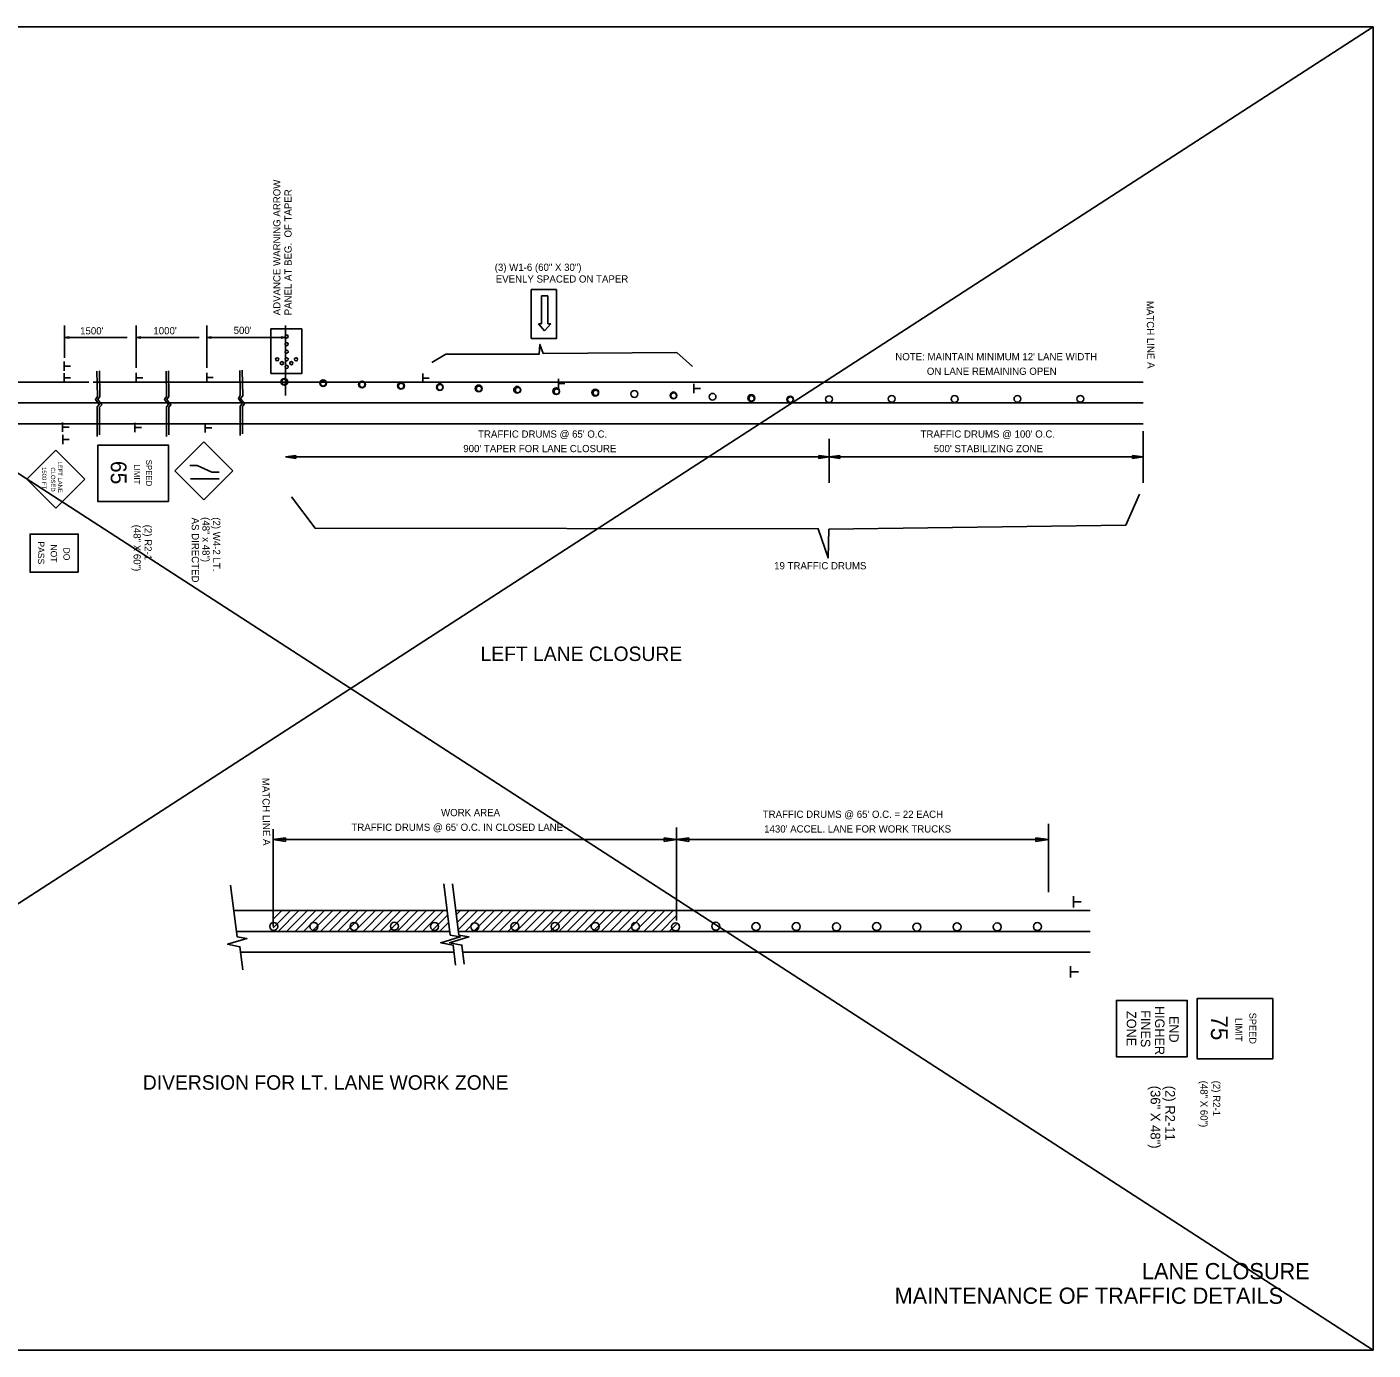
# Model space of a CAD drawing. Extents: x 1374027 to 1374537, y 380415 to 381405.
# Drawn here: x 1374085.2 to 1374197.1, y 380635.2 to 380745.2 of the extents above; entities that cross this region are included whole.
import ezdxf

# ---------------------------------------------------------------- set-up
doc = ezdxf.new("R2010")
doc.units = 0
for name, color, linetype in [('Default', 7, 'Continuous'), ('DSN_DRFT_Junk-No-Plot', 7, 'Continuous'), ('R_Border Notes', 7, 'Continuous'), ('R_MOT', 7, 'Continuous')]:
    doc.layers.add(name, color=color, linetype=linetype)

msp = doc.modelspace()

# ---------------------------------------------------------------- linework, layer by layer
at = {"layer": 'Default'}
for p, q in [((1374127.96, 380722.82), (1374127.96, 380720.49)), ((1374127.96, 380722.82), (1374128.48, 380722.82)), ((1374128.48, 380722.82), (1374128.48, 380720.49)), ((1374088.31, 380720.34), (1374088.31, 380717.66)), ((1374094.28, 380720.34), (1374094.28, 380716.82)), ((1374100.14, 380720.34), (1374100.14, 380716.82)), ((1374106.68, 380720.34), (1374106.68, 380716.82)), ((1374127.96, 380720.49), (1374127.7, 380720.49)), ((1374127.7, 380720.49), (1374128.22, 380719.92)), ((1374128.22, 380719.92), (1374128.74, 380720.49)), ((1374128.48, 380720.49), (1374128.74, 380720.49)), ((1374088.69, 380719.42), (1374088.31, 380719.36)), ((1374088.31, 380719.36), (1374093.53, 380719.36)), ((1374088.69, 380719.3), (1374088.31, 380719.36)), ((1374088.69, 380719.41), (1374088.38, 380719.36)), ((1374088.69, 380719.31), (1374088.38, 380719.36)), ((1374088.69, 380719.4), (1374088.44, 380719.36)), ((1374088.69, 380719.32), (1374088.44, 380719.36)), ((1374088.69, 380719.39), (1374088.5, 380719.36)), ((1374088.69, 380719.33), (1374088.5, 380719.36)), ((1374088.69, 380719.38), (1374088.57, 380719.36)), ((1374088.69, 380719.34), (1374088.57, 380719.36)), ((1374088.69, 380719.37), (1374088.63, 380719.36)), ((1374088.69, 380719.35), (1374088.63, 380719.36)), ((1374088.69, 380719.3), (1374088.69, 380719.42)), ((1374094.66, 380719.42), (1374094.28, 380719.36)), ((1374094.28, 380719.36), (1374099.5, 380719.36)), ((1374094.66, 380719.3), (1374094.28, 380719.36)), ((1374094.66, 380719.41), (1374094.35, 380719.36)), ((1374094.66, 380719.31), (1374094.35, 380719.36)), ((1374094.66, 380719.4), (1374094.41, 380719.36)), ((1374094.66, 380719.32), (1374094.41, 380719.36)), ((1374094.66, 380719.39), (1374094.47, 380719.36)), ((1374094.66, 380719.33), (1374094.47, 380719.36)), ((1374094.66, 380719.38), (1374094.54, 380719.36)), ((1374094.66, 380719.34), (1374094.54, 380719.36)), ((1374094.66, 380719.37), (1374094.6, 380719.36)), ((1374094.66, 380719.35), (1374094.6, 380719.36)), ((1374094.66, 380719.3), (1374094.66, 380719.42)), ((1374100.51, 380719.42), (1374100.14, 380719.36)), ((1374100.14, 380719.36), (1374106.68, 380719.36)), ((1374100.51, 380719.3), (1374100.14, 380719.36)), ((1374100.51, 380719.41), (1374100.2, 380719.36)), ((1374100.51, 380719.31), (1374100.2, 380719.36)), ((1374100.51, 380719.4), (1374100.26, 380719.36)), ((1374100.51, 380719.32), (1374100.26, 380719.36)), ((1374100.51, 380719.39), (1374100.32, 380719.36)), ((1374100.51, 380719.33), (1374100.32, 380719.36)), ((1374100.51, 380719.38), (1374100.39, 380719.36)), ((1374100.51, 380719.34), (1374100.39, 380719.36)), ((1374100.51, 380719.37), (1374100.45, 380719.36)), ((1374100.51, 380719.35), (1374100.45, 380719.36)), ((1374100.51, 380719.3), (1374100.51, 380719.42)), ((1374106.31, 380719.42), (1374106.68, 380719.36)), ((1374106.31, 380719.42), (1374106.31, 380719.3)), ((1374106.31, 380719.41), (1374106.62, 380719.36)), ((1374106.31, 380719.4), (1374106.56, 380719.36)), ((1374106.31, 380719.39), (1374106.49, 380719.36)), ((1374106.31, 380719.38), (1374106.43, 380719.36)), ((1374106.31, 380719.37), (1374106.37, 380719.36)), ((1374106.31, 380719.3), (1374106.68, 380719.36)), ((1374106.31, 380719.34), (1374106.43, 380719.36)), ((1374106.31, 380719.32), (1374106.56, 380719.36)), ((1374106.31, 380719.31), (1374106.62, 380719.36)), ((1374106.31, 380719.33), (1374106.49, 380719.36)), ((1374106.31, 380719.35), (1374106.37, 380719.36)), ((1374106.68, 380718.06), (1374106.68, 380714.54)), ((1374088.28, 380716.57), (1374088.28, 380717.35)), ((1374088.28, 380715.6), (1374088.28, 380716.39)), ((1374088.29, 380716.96), (1374088.82, 380716.96)), ((1374094.28, 380715.62), (1374094.28, 380716.41)), ((1374100.14, 380715.65), (1374100.14, 380716.43)), ((1374118.09, 380716.36), (1374118.09, 380715.58)), ((1374082.03, 380715.65), (1374090.33, 380715.65)), ((1374088.29, 380715.99), (1374088.82, 380715.99)), ((1374090.69, 380715.64), (1374106.68, 380715.64)), ((1374094.3, 380716.01), (1374094.83, 380716.01)), ((1374100.15, 380716.03), (1374100.68, 380716.03)), ((1374106.68, 380715.65), (1374177.96, 380715.65)), ((1374118.1, 380715.97), (1374118.63, 380715.97)), ((1374129.36, 380715.93), (1374129.36, 380715.15)), ((1374129.37, 380715.54), (1374129.9, 380715.54)), ((1374140.63, 380715.5), (1374140.63, 380714.72)), ((1374140.64, 380715.12), (1374141.17, 380715.12)), ((1374082.03, 380713.91), (1374090.69, 380713.91)), ((1374090.69, 380713.91), (1374106.68, 380713.91)), ((1374106.68, 380713.91), (1374177.96, 380713.91)), ((1374082.03, 380712.17), (1374091.61, 380712.17)), ((1374088.15, 380711.5), (1374088.15, 380712.28)), ((1374088.16, 380711.89), (1374088.7, 380711.89)), ((1374090.69, 380712.17), (1374106.68, 380712.17)), ((1374094.16, 380711.48), (1374094.16, 380712.26)), ((1374094.17, 380711.86), (1374094.7, 380711.86)), ((1374100.01, 380711.45), (1374100.01, 380712.24)), ((1374100.02, 380711.84), (1374100.55, 380711.84)), ((1374106.68, 380712.17), (1374177.96, 380712.17)), ((1374088.16, 380710.49), (1374088.16, 380711.27)), ((1374088.17, 380710.88), (1374088.7, 380710.88)), ((1374099.9, 380710.67), (1374097.49, 380708.26)), ((1374099.9, 380710.67), (1374102.31, 380708.26)), ((1374151.88, 380710.92), (1374151.88, 380707.26)), ((1374177.96, 380711.57), (1374177.96, 380707.26)), ((1374085.19, 380707.57), (1374087.59, 380709.98)), ((1374090, 380707.58), (1374087.59, 380709.98)), ((1374098.74, 380708.72), (1374099.35, 380708.72)), ((1374099.35, 380708.72), (1374100.57, 380708.16)), ((1374106.68, 380709.42), (1374107.55, 380709.55)), ((1374151.88, 380709.42), (1374106.68, 380709.42)), ((1374107.55, 380709.29), (1374106.68, 380709.42)), ((1374107.55, 380709.55), (1374107.55, 380709.29)), ((1374151.01, 380709.29), (1374151.01, 380709.55)), ((1374151.01, 380709.55), (1374151.88, 380709.42)), ((1374151.88, 380709.42), (1374151.01, 380709.29)), ((1374151.88, 380709.42), (1374152.75, 380709.55)), ((1374177.96, 380709.42), (1374151.88, 380709.42)), ((1374152.75, 380709.29), (1374151.88, 380709.42)), ((1374152.75, 380709.55), (1374152.75, 380709.29)), ((1374177.09, 380709.29), (1374177.09, 380709.55)), ((1374177.09, 380709.55), (1374177.96, 380709.42)), ((1374177.96, 380709.42), (1374177.09, 380709.29)), ((1374087.6, 380705.17), (1374085.19, 380707.57)), ((1374087.6, 380705.17), (1374090, 380707.58)), ((1374097.49, 380708.26), (1374099.9, 380705.85)), ((1374098.79, 380707.6), (1374101.16, 380707.6)), ((1374102.31, 380708.26), (1374099.9, 380705.85)), ((1374100.57, 380708.16), (1374101.16, 380708.16)), ((1374105.65, 380678.47), (1374105.65, 380670.4)), ((1374139.18, 380678.63), (1374139.18, 380670.9)), ((1374170.09, 380678.93), (1374170.09, 380673.25)), ((1374105.65, 380677.62), (1374106.68, 380677.77)), ((1374139.18, 380677.62), (1374105.65, 380677.62)), ((1374106.68, 380677.46), (1374105.65, 380677.62)), ((1374106.68, 380677.77), (1374106.68, 380677.46)), ((1374138.15, 380677.46), (1374138.15, 380677.77)), ((1374138.15, 380677.77), (1374139.18, 380677.62)), ((1374139.18, 380677.62), (1374138.15, 380677.46)), ((1374139.18, 380677.62), (1374140.21, 380677.77)), ((1374170.09, 380677.62), (1374139.18, 380677.62)), ((1374140.21, 380677.46), (1374139.18, 380677.62)), ((1374140.21, 380677.77), (1374140.21, 380677.46)), ((1374169.06, 380677.46), (1374169.06, 380677.77)), ((1374169.06, 380677.77), (1374170.09, 380677.62)), ((1374170.09, 380677.62), (1374169.06, 380677.46)), ((1374105.65, 380675.51), (1374105.65, 380670.4)), ((1374105.65, 380675.51), (1374105.65, 380670.4)), ((1374105.65, 380675.51), (1374105.65, 380670.4)), ((1374172.18, 380671.98), (1374172.18, 380672.91)), ((1374102.38, 380671.72), (1374105.65, 380671.72)), ((1374105.65, 380671.72), (1374120.12, 380671.72)), ((1374105.65, 380670.28), (1374107.09, 380671.72)), ((1374105.65, 380670.99), (1374106.38, 380671.72)), ((1374106.06, 380669.98), (1374107.79, 380671.72)), ((1374106.76, 380669.98), (1374108.56, 380671.78)), ((1374107.47, 380669.98), (1374109.21, 380671.72)), ((1374108.18, 380669.98), (1374109.91, 380671.72)), ((1374108.88, 380669.98), (1374110.62, 380671.72)), ((1374109.59, 380669.98), (1374111.33, 380671.72)), ((1374110.3, 380669.98), (1374112.04, 380671.72)), ((1374111, 380669.98), (1374112.74, 380671.72)), ((1374111.71, 380669.98), (1374113.45, 380671.72)), ((1374112.42, 380669.98), (1374114.16, 380671.72)), ((1374113.13, 380669.98), (1374114.86, 380671.72)), ((1374113.83, 380669.98), (1374115.57, 380671.72)), ((1374114.54, 380669.98), (1374116.28, 380671.72)), ((1374115.25, 380669.98), (1374116.99, 380671.72)), ((1374115.95, 380669.98), (1374117.69, 380671.72)), ((1374116.66, 380669.98), (1374118.4, 380671.72)), ((1374117.37, 380669.98), (1374119.11, 380671.72)), ((1374118.08, 380669.98), (1374119.81, 380671.72)), ((1374120.84, 380671.72), (1374139.18, 380671.72)), ((1374120.9, 380671.39), (1374121.23, 380671.72)), ((1374120.97, 380670.76), (1374121.94, 380671.72)), ((1374121.05, 380670.13), (1374122.64, 380671.72)), ((1374121.61, 380669.98), (1374123.35, 380671.72)), ((1374122.32, 380669.98), (1374124.06, 380671.72)), ((1374123.03, 380669.98), (1374124.76, 380671.72)), ((1374123.73, 380669.98), (1374125.47, 380671.72)), ((1374124.44, 380669.98), (1374126.18, 380671.72)), ((1374125.15, 380669.98), (1374126.89, 380671.72)), ((1374125.85, 380669.98), (1374127.59, 380671.72)), ((1374126.56, 380669.98), (1374128.3, 380671.72)), ((1374127.27, 380669.98), (1374129.01, 380671.72)), ((1374127.98, 380669.98), (1374129.71, 380671.72)), ((1374128.68, 380669.98), (1374130.42, 380671.72)), ((1374129.39, 380669.98), (1374131.13, 380671.72)), ((1374130.1, 380669.98), (1374131.84, 380671.72)), ((1374130.8, 380669.98), (1374132.54, 380671.72)), ((1374131.51, 380669.98), (1374133.25, 380671.72)), ((1374132.22, 380669.98), (1374133.96, 380671.72)), ((1374132.93, 380669.98), (1374134.66, 380671.72)), ((1374133.63, 380669.98), (1374135.37, 380671.72)), ((1374134.34, 380669.98), (1374136.08, 380671.72)), ((1374135.05, 380669.98), (1374136.78, 380671.72)), ((1374135.75, 380669.98), (1374137.49, 380671.72)), ((1374136.46, 380669.98), (1374138.2, 380671.72)), ((1374137.17, 380669.98), (1374138.91, 380671.72)), ((1374139.18, 380671.72), (1374173.57, 380671.72)), ((1374172.19, 380672.44), (1374172.83, 380672.44)), ((1374118.78, 380669.98), (1374120.17, 380671.37)), ((1374119.49, 380669.98), (1374120.25, 380670.74)), ((1374137.87, 380669.98), (1374139.18, 380671.29)), ((1374138.58, 380669.98), (1374139.18, 380670.58)), ((1374102.6, 380669.98), (1374105.58, 380669.98)), ((1374105.58, 380669.98), (1374120.27, 380669.98)), ((1374121.06, 380669.98), (1374139.18, 380669.98)), ((1374139.18, 380669.98), (1374173.57, 380669.98)), ((1374102.95, 380668.25), (1374105.63, 380668.25)), ((1374105.63, 380668.25), (1374120.69, 380668.25)), ((1374121.45, 380668.25), (1374139.18, 380668.25)), ((1374139.18, 380668.25), (1374173.57, 380668.25)), ((1374171.94, 380666.16), (1374171.94, 380667.08)), ((1374171.95, 380666.62), (1374172.59, 380666.62))]:
    msp.add_line(p, q, dxfattribs=at)
for points in [[(1374127.11, 380719.26), (1374127.11, 380723.34), (1374129.2, 380723.34), (1374129.2, 380719.26)], [(1374105.46, 380716.35), (1374105.46, 380720.07), (1374108.03, 380720.07), (1374108.03, 380716.35)], [(1374096.96, 380705.73), (1374091.07, 380705.73), (1374091.07, 380710.4), (1374096.96, 380710.4)], [(1374089.45, 380699.84), (1374085.45, 380699.84), (1374085.45, 380703.01), (1374089.45, 380703.01)], [(1374188.75, 380659.4), (1374182.45, 380659.4), (1374182.45, 380664.4), (1374188.75, 380664.4)]]:
    msp.add_lwpolyline(points, close=True, dxfattribs=at)
for points in [[(1374118.84, 380717.28), (1374120, 380717.96), (1374127.76, 380717.96), (1374127.83, 380718.78), (1374128.1, 380718.03), (1374139.2, 380718.1), (1374140.5, 380716.94)], [(1374091.01, 380716.56), (1374091.05, 380714.45), (1374090.88, 380714.21), (1374091.2, 380713.78), (1374091.03, 380713.58), (1374091.03, 380711.13)], [(1374091.21, 380716.58), (1374091.25, 380714.44), (1374091.08, 380714.2), (1374091.4, 380713.77), (1374091.23, 380713.57), (1374091.23, 380711.27)], [(1374096.76, 380716.56), (1374096.79, 380714.45), (1374096.63, 380714.21), (1374096.95, 380713.78), (1374096.78, 380713.58), (1374096.78, 380711.13)], [(1374096.96, 380716.58), (1374096.99, 380714.44), (1374096.83, 380714.2), (1374097.15, 380713.77), (1374096.98, 380713.57), (1374096.98, 380711.27)], [(1374102.89, 380716.62), (1374102.92, 380714.52), (1374102.76, 380714.27), (1374103.07, 380713.84), (1374102.91, 380713.64), (1374102.9, 380711.2)], [(1374103.09, 380716.64), (1374103.12, 380714.51), (1374102.95, 380714.27), (1374103.27, 380713.83), (1374103.1, 380713.63), (1374103.1, 380711.34)], [(1374107.17, 380706.11), (1374109.14, 380703.49), (1374150.97, 380703.45), (1374151.78, 380701.03), (1374151.85, 380703.41), (1374176.52, 380703.74), (1374177.66, 380706.34)], [(1374102.12, 380673.82), (1374102.65, 380669.54), (1374103.48, 380669.39), (1374101.87, 380668.91), (1374102.89, 380668.71), (1374103.12, 380666.79)], [(1374119.84, 380673.94), (1374120.37, 380669.67), (1374121.2, 380669.52), (1374119.59, 380669.04), (1374120.61, 380668.84), (1374120.82, 380667.16)], [(1374120.57, 380673.94), (1374121.1, 380669.67), (1374121.93, 380669.52), (1374120.32, 380669.04), (1374121.34, 380668.84), (1374121.53, 380667.26)]]:
    msp.add_lwpolyline(points, dxfattribs=at)
for centre, radius in [((1374106.77, 380719.44), 0.131), ((1374106.77, 380718.8), 0.131), ((1374105.99, 380717.54), 0.131), ((1374106.77, 380718.17), 0.131), ((1374106.77, 380717.54), 0.131), ((1374107.56, 380717.54), 0.131), ((1374106.38, 380717.22), 0.131), ((1374106.77, 380716.91), 0.131), ((1374107.17, 380717.22), 0.131), ((1374106.58, 380715.67), 0.281), ((1374106.56, 380715.67), 0.229), ((1374106.58, 380715.67), 0.229), ((1374109.81, 380715.56), 0.281), ((1374109.81, 380715.55), 0.229), ((1374113.04, 380715.45), 0.281), ((1374113.05, 380715.44), 0.229), ((1374116.28, 380715.34), 0.281), ((1374116.29, 380715.32), 0.229), ((1374119.51, 380715.23), 0.281), ((1374119.52, 380715.21), 0.229), ((1374122.74, 380715.12), 0.281), ((1374122.76, 380715.09), 0.229), ((1374125.93, 380715.01), 0.281), ((1374126, 380714.98), 0.229), ((1374129.18, 380714.89), 0.281), ((1374129.23, 380714.86), 0.229), ((1374132.43, 380714.77), 0.281), ((1374132.47, 380714.75), 0.229), ((1374135.68, 380714.66), 0.281), ((1374138.93, 380714.54), 0.281), ((1374138.94, 380714.52), 0.229), ((1374142.18, 380714.43), 0.281), ((1374145.4, 380714.32), 0.281), ((1374145.42, 380714.29), 0.229), ((1374148.63, 380714.2), 0.281), ((1374148.65, 380714.18), 0.229), ((1374151.86, 380714.22), 0.281), ((1374157.07, 380714.25), 0.281), ((1374162.3, 380714.24), 0.281), ((1374167.52, 380714.25), 0.281), ((1374172.75, 380714.25), 0.281), ((1374105.7, 380670.39), 0.333), ((1374109.04, 380670.39), 0.333), ((1374112.38, 380670.39), 0.333), ((1374115.73, 380670.41), 0.333), ((1374119.07, 380670.39), 0.333), ((1374122.41, 380670.37), 0.333), ((1374125.75, 380670.39), 0.333), ((1374129.09, 380670.39), 0.333), ((1374132.43, 380670.39), 0.333), ((1374135.77, 380670.38), 0.333), ((1374139.11, 380670.36), 0.333), ((1374142.45, 380670.41), 0.333), ((1374145.79, 380670.38), 0.333), ((1374149.14, 380670.38), 0.333), ((1374152.48, 380670.36), 0.333), ((1374155.82, 380670.38), 0.333), ((1374159.16, 380670.34), 0.333), ((1374162.5, 380670.36), 0.333), ((1374165.84, 380670.36), 0.333), ((1374169.18, 380670.38), 0.333)]:
    msp.add_circle(centre, radius, dxfattribs=at)
at = {"layer": 'DSN_DRFT_Junk-No-Plot'}
for p, q in [((1374027.08, 380635.17), (1374197.08, 380745.17)), ((1374027.08, 380745.17), (1374197.08, 380635.17))]:
    msp.add_line(p, q, dxfattribs=at)
for points in [[(1374027.08, 380745.17), (1374197.08, 380745.17), (1374197.08, 380635.17), (1374027.08, 380635.17)], [(1374027.08, 380745.17), (1374027.08, 380635.17), (1374197.08, 380635.17), (1374197.08, 380745.17)]]:
    msp.add_lwpolyline(points, close=True, dxfattribs=at)
at = {"layer": 'R_MOT'}
msp.add_lwpolyline([(1374181.64, 380659.56), (1374175.75, 380659.56), (1374175.75, 380664.24), (1374181.64, 380664.24)], close=True, dxfattribs=at)

# ---------------------------------------------------------------- texts
at = {"layer": 'Default'}
for s, height, rotation, p in [('ADVANCE WARNING ARROW', 0.6, 90, (1374106.26, 380721.2)), ('PANEL AT BEG.  OF TAPER', 0.6, 90, (1374107.19, 380721.2)), ('(3) W1-6 (60" X 30")', 0.6, 0.0075, (1374124.07, 380724.89)), ('EVENLY SPACED ON TAPER', 0.6, 0.0075, (1374124.16, 380723.92)), ('MATCH LINE A', 0.6, 270.8059, (1374178.25, 380722.39)), ('1500 FT', 0.357, 270.0006, (1374086.45, 380708.58)), ('CLOSED', 0.354, 270.1003, (1374087.18, 380708.55)), ('LEFT LANE', 0.354, 270.1004, (1374087.77, 380709.05)), ('65', 1.304, 270, (1374092.16, 380709.09)), ('LIMIT', 0.487, 270, (1374094.09, 380708.81)), ('SPEED', 0.487, 270, (1374095.09, 380709.19)), ('AS DIRECTED ', 0.6, 270, (1374098.89, 380704.38)), ('(48" x 48")', 0.6, 270, (1374099.77, 380704.42)), ('(2) W4-2 LT.', 0.6, 270, (1374100.65, 380704.41)), ('(48" X 60")', 0.6, 270, (1374094.05, 380703.79)), ('(2) R2-1', 0.6, 270, (1374094.96, 380703.79)), ('PASS', 0.532, 270, (1374086.1, 380702.4)), ('NOT', 0.532, 270, (1374087.16, 380702.15)), ('DO', 0.532, 270, (1374088.22, 380701.89)), ('MATCH LINE A', 0.6, 270.8059, (1374104.74, 380682.74)), ('75', 1.396, 270, (1374183.61, 380663)), ('LIMIT', 0.573, 270, (1374185.63, 380662.78)), ('SPEED', 0.573, 270, (1374186.8, 380663.22)), ('(48" X 60")', 0.6, 270, (1374182.73, 380657.57)), ('(2) R2-1', 0.6, 270, (1374183.78, 380657.57))]:
    msp.add_text(s, height=height, rotation=rotation, dxfattribs=at).set_placement(p)
for s, height, p in [("1500'", 0.6, (1374089.61, 380719.61)), ("1000'", 0.6, (1374095.7, 380719.62)), ("500'", 0.6, (1374102.37, 380719.65)), ("NOTE: MAINTAIN MINIMUM 12' LANE WIDTH", 0.6, (1374157.37, 380717.46)), (' ON LANE REMAINING OPEN', 0.6, (1374159.77, 380716.25)), ("TRAFFIC DRUMS @ 65' O.C.", 0.6, (1374122.69, 380711.03)), ("TRAFFIC DRUMS @ 100' O.C.", 0.6, (1374159.47, 380711.03)), ("900' TAPER FOR LANE CLOSURE", 0.6, (1374121.46, 380709.82)), ("500' STABILIZING ZONE", 0.6, (1374160.57, 380709.82)), ('19 TRAFFIC DRUMS', 0.6, (1374147.3, 380700.08)), ('LEFT LANE CLOSURE', 1.2, (1374122.89, 380692.46)), ('WORK AREA', 0.6, (1374119.61, 380679.56)), ("TRAFFIC DRUMS @ 65' O.C. = 22 EACH", 0.6, (1374146.35, 380679.42)), ("TRAFFIC DRUMS @ 65' O.C. IN CLOSED LANE", 0.6, (1374112.16, 380678.34)), ("1430' ACCEL. LANE FOR WORK TRUCKS", 0.6, (1374146.47, 380678.2)), ('DIVERSION FOR LT. LANE WORK ZONE', 1.2, (1374094.82, 380656.82))]:
    msp.add_text(s, height=height, dxfattribs=at).set_placement(p)
at = {"layer": 'R_Border Notes'}
for s, p in [('LANE CLOSURE', (1374177.87, 380641.06)), ('MAINTENANCE OF TRAFFIC DETAILS', (1374157.31, 380639.02))]:
    msp.add_text(s, height=1.35, dxfattribs=at).set_placement(p)
at = {"layer": 'R_MOT'}
for s, height, p in [('HIGHER', 0.784, (1374178.96, 380663.78)), ('ZONE', 0.784, (1374176.61, 380663.36)), ('FINES', 0.784, (1374177.78, 380663.43)), ('END', 0.784, (1374180.14, 380662.95)), ('(36" X 48")', 0.81, (1374178.59, 380657.15)), ('(2) R2-11', 0.81, (1374179.81, 380657.15))]:
    msp.add_text(s, height=height, rotation=270, dxfattribs=at).set_placement(p)

doc.saveas('drawing.dxf')
